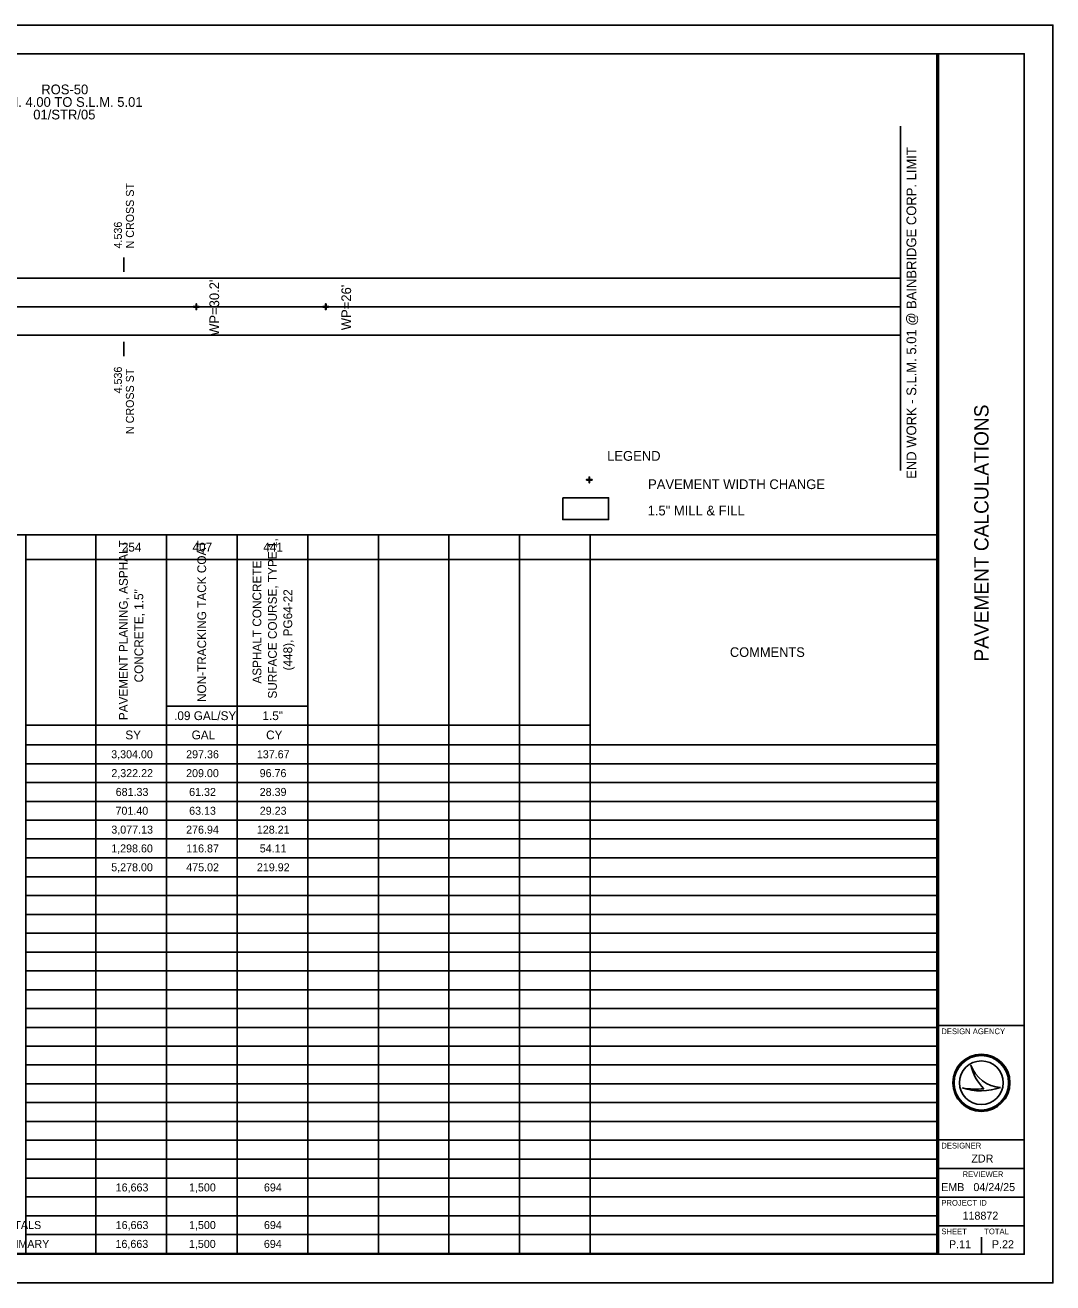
# Model space of a CAD drawing. Extents: x 0 to 34, y 0 to 42.2.
# Drawn here: x 16.03 to 34, y 0 to 22 of the extents above; entities that cross this region are included whole.
import ezdxf

# ---------------------------------------------------------------- set-up
doc = ezdxf.new("R2010")
doc.units = 0
for name, color, linetype in [('Default', 7, 'Continuous'), ('SH_Border', 7, 'Continuous'), ('SH_Cut_Line', 7, 'Continuous'), ('SH_Data', 7, 'Continuous'), ('SH_Text', 7, 'Continuous'), ('TX_P_1', 7, 'Continuous')]:
    doc.layers.add(name, color=color, linetype=linetype)

msp = doc.modelspace()

# ---------------------------------------------------------------- linework, layer by layer
at = {"layer": 'Default'}
for p, q in [((18.97, 17.079), (19.015, 17.079)), ((18.97, 17.079), (18.97, 17.069)), ((18.97, 17.069), (19.015, 17.069)), ((19.015, 17.124), (19.025, 17.124)), ((19.015, 17.079), (19.015, 17.124)), ((19.015, 17.074), (19.025, 17.074)), ((19.015, 17.024), (19.015, 17.069)), ((19.025, 17.024), (19.015, 17.024)), ((19.02, 17.069), (19.02, 17.079)), ((19.025, 17.079), (19.025, 17.124)), ((19.025, 17.079), (19.07, 17.079)), ((19.025, 17.024), (19.025, 17.069)), ((19.025, 17.069), (19.07, 17.069)), ((19.07, 17.079), (19.07, 17.069)), ((21.234, 17.079), (21.279, 17.079)), ((21.234, 17.079), (21.234, 17.069)), ((21.234, 17.069), (21.279, 17.069)), ((21.279, 17.124), (21.289, 17.124)), ((21.279, 17.079), (21.279, 17.124)), ((21.279, 17.074), (21.289, 17.074)), ((21.279, 17.024), (21.279, 17.069)), ((21.289, 17.024), (21.279, 17.024)), ((21.284, 17.069), (21.284, 17.079)), ((21.289, 17.079), (21.289, 17.124)), ((21.289, 17.079), (21.334, 17.079)), ((21.289, 17.024), (21.289, 17.069)), ((21.289, 17.069), (21.334, 17.069)), ((21.334, 17.079), (21.334, 17.069)), ((25.888, 14.096), (25.898, 14.096)), ((25.888, 14.051), (25.888, 14.096)), ((25.898, 14.051), (25.898, 14.096)), ((25.843, 14.051), (25.888, 14.051)), ((25.843, 14.051), (25.843, 14.041)), ((25.843, 14.041), (25.888, 14.041)), ((25.888, 14.046), (25.898, 14.046)), ((25.888, 13.996), (25.888, 14.041)), ((25.898, 13.996), (25.888, 13.996)), ((25.893, 14.041), (25.893, 14.051)), ((25.898, 14.051), (25.943, 14.051)), ((25.898, 13.996), (25.898, 14.041)), ((25.898, 14.041), (25.943, 14.041)), ((25.943, 14.051), (25.943, 14.041))]:
    msp.add_line(p, q, dxfattribs=at)
for points in [[(18.97, 17.069), (18.97, 17.079), (19.015, 17.079), (19.015, 17.124), (19.025, 17.124), (19.025, 17.079), (19.07, 17.079), (19.07, 17.069), (19.025, 17.069), (19.025, 17.024), (19.015, 17.024), (19.015, 17.069)], [(21.234, 17.069), (21.234, 17.079), (21.279, 17.079), (21.279, 17.124), (21.289, 17.124), (21.289, 17.079), (21.334, 17.079), (21.334, 17.069), (21.289, 17.069), (21.289, 17.024), (21.279, 17.024), (21.279, 17.069)], [(25.843, 14.041), (25.843, 14.051), (25.888, 14.051), (25.888, 14.096), (25.898, 14.096), (25.898, 14.051), (25.943, 14.051), (25.943, 14.041), (25.898, 14.041), (25.898, 13.996), (25.888, 13.996), (25.888, 14.041)]]:
    msp.add_lwpolyline(points, close=True, dxfattribs=at)
at = {"layer": 'SH_Border'}
for p, q in [((32, 0.5), (32, 21.5)), ((32, 4.5), (33.5, 4.5)), ((32, 2.5), (33.5, 2.5)), ((32, 2), (33.5, 2)), ((32, 1.5), (33.5, 1.5)), ((32, 1), (33.5, 1))]:
    msp.add_line(p, q, dxfattribs=at)
msp.add_lwpolyline([(1.5, 21.5), (33.5, 21.5), (33.5, 0.5), (1.5, 0.5)], close=True, dxfattribs=at)
at = {"layer": 'SH_Cut_Line'}
msp.add_lwpolyline([(0, 0), (34, 0), (34, 22), (0, 22)], close=True, dxfattribs=at)
at = {"layer": 'SH_Data'}
for p, q in [((32.567, 3.81), (32.567, 3.81)), ((32.417, 3.41), (32.417, 3.41)), ((32.75, 3.5), (32.75, 3.5)), ((33.087, 3.419), (33.087, 3.419)), ((32.375, 0.675), (32.375, 0.675)), ((32.75, 0.5), (32.75, 0.8))]:
    msp.add_line(p, q, dxfattribs=at)
for radius in [0.5, 0.477, 0.477, 0.382]:
    msp.add_circle((32.75, 3.5), radius, dxfattribs=at)
for centre, radius, start, end in [((33.116, 3.998), 0.58, 198.9257, 198.9319), ((33.347, 3.97), 0.796, 191.6379, 191.6421), ((33.116, 3.998), 0.58, 198.9319, 267.1657), ((33.347, 3.97), 0.796, 191.6421, 226.0947), ((32.739, 4.37), 1.013, 251.4576, 290.0832), ((32.648, 4.654), 1.266, 259.4964, 259.4995), ((32.739, 4.37), 1.013, 251.4527, 251.4576), ((32.648, 4.654), 1.266, 259.4995, 276.6672)]:
    msp.add_arc(centre, radius, start, end, dxfattribs=at)
at = {"layer": 'SH_Text'}
for p, q in [((1.5, 21.5), (31.971, 21.5)), ((31.971, 21.5), (31.971, 0.516)), ((31.335, 20.232), (31.335, 14.211)), ((17.751, 17.687), (17.751, 17.937)), ((2.18, 17.574), (31.335, 17.574)), ((2.18, 17.074), (31.335, 17.072)), ((2.18, 16.576), (31.335, 16.576)), ((17.751, 16.461), (17.751, 16.211)), ((13.891, 13.084), (16.038, 13.084)), ((16.016, 13.084), (31.971, 13.084)), ((16.038, 13.084), (16.038, 0.516)), ((17.262, 13.084), (17.262, 0.516)), ((18.498, 13.084), (18.498, 0.516)), ((19.733, 13.084), (19.733, 0.516)), ((20.968, 13.084), (20.968, 0.516)), ((22.204, 13.084), (22.204, 0.516)), ((23.439, 13.084), (23.439, 0.516)), ((24.674, 13.084), (24.674, 0.516)), ((25.909, 13.084), (25.909, 0.516)), ((16.038, 12.655), (31.971, 12.655)), ((18.498, 10.086), (20.968, 10.086)), ((16.038, 9.756), (25.909, 9.756)), ((16.038, 9.411), (31.971, 9.411)), ((16.038, 9.081), (31.971, 9.081)), ((16.038, 8.752), (31.971, 8.752)), ((16.038, 8.422), (31.971, 8.422)), ((16.038, 8.093), (31.971, 8.093)), ((16.038, 7.764), (31.971, 7.764)), ((16.038, 7.434), (31.971, 7.434)), ((16.038, 7.105), (31.971, 7.105)), ((16.038, 6.775), (31.971, 6.775)), ((16.038, 6.446), (31.971, 6.446)), ((16.038, 6.116), (31.971, 6.116)), ((16.038, 5.787), (31.971, 5.787)), ((16.038, 5.458), (31.971, 5.458)), ((16.038, 5.128), (31.971, 5.128)), ((16.038, 4.799), (31.971, 4.799)), ((16.038, 4.469), (31.971, 4.469)), ((16.038, 4.14), (31.971, 4.14)), ((16.038, 3.811), (31.971, 3.811)), ((16.038, 3.481), (31.971, 3.481)), ((16.038, 3.152), (31.971, 3.152)), ((16.038, 2.822), (31.971, 2.822)), ((16.038, 2.493), (31.971, 2.493)), ((16.038, 2.164), (31.971, 2.164)), ((16.038, 1.834), (31.971, 1.834)), ((16.038, 1.505), (31.971, 1.505)), ((16.038, 1.175), (31.971, 1.175)), ((16.038, 0.846), (31.971, 0.846)), ((1.5, 0.516), (16.038, 0.516)), ((16.016, 0.516), (31.971, 0.516))]:
    msp.add_line(p, q, dxfattribs=at)
for points in [[(2.18, 17.574), (31.335, 17.574), (31.335, 16.575), (2.18, 16.575)], [(25.43, 13.732), (26.23, 13.732), (26.23, 13.352), (25.43, 13.352)]]:
    msp.add_lwpolyline(points, close=True, dxfattribs=at)
at = {"layer": 'TX_P_1'}
msp.add_lwpolyline([(25.43, 13.732), (26.23, 13.732), (26.23, 13.352), (25.43, 13.352)], close=True, dxfattribs=at)

# ---------------------------------------------------------------- texts
at = {"layer": 'SH_Data'}
msp.add_text('PAVEMENT CALCULATIONS', height=0.25, rotation=90, dxfattribs=at).set_placement((32.875, 10.868))
for s, height, p in [('DESIGN AGENCY', 0.1, (32.05, 4.35)), ('DESIGNER', 0.1, (32.05, 2.35)), ('ZDR', 0.14, (32.575, 2.105)), ('REVIEWER', 0.1, (32.422, 1.85)), ('EMB', 0.14, (32.047, 1.605)), ('04/24/25', 0.14, (32.611, 1.605)), ('PROJECT ID', 0.1, (32.05, 1.35)), ('118872', 0.14, (32.421, 1.105)), ('SHEET', 0.1, (32.05, 0.85)), ('TOTAL', 0.1, (32.8, 0.85)), ('P.11', 0.14, (32.184, 0.605)), ('P.22', 0.14, (32.935, 0.605))]:
    msp.add_text(s, height=height, dxfattribs=at).set_placement(p)
at = {"layer": 'SH_Text'}
for s, height, p in [('ROS-50', 0.17, (16.309, 20.791)), ('S.L.M. 4.00 TO S.L.M. 5.01', 0.17, (15.313, 20.571)), ('01/STR/05', 0.17, (16.169, 20.351)), ('254', 0.154, (17.717, 12.792)), ('407', 0.154, (18.954, 12.792)), ('441', 0.154, (20.191, 12.792)), ('COMMENTS', 0.168, (28.352, 10.949)), ('.09 GAL/SY', 0.154, (18.632, 9.844)), ('1.5"', 0.154, (20.177, 9.844)), ('SY', 0.154, (17.779, 9.507)), ('GAL', 0.154, (18.938, 9.507)), ('CY', 0.154, (20.241, 9.507)), ('3,304.00', 0.14, (17.532, 9.176)), ('297.36', 0.14, (18.843, 9.176)), ('137.67', 0.14, (20.079, 9.176)), ('2,322.22', 0.14, (17.534, 8.846)), ('209.00', 0.14, (18.842, 8.846)), ('96.76', 0.14, (20.128, 8.846)), ('681.33', 0.14, (17.61, 8.517)), ('61.32', 0.14, (18.895, 8.517)), ('28.39', 0.14, (20.129, 8.517)), ('701.40', 0.14, (17.607, 8.188)), ('63.13', 0.14, (18.895, 8.188)), ('29.23', 0.14, (20.13, 8.188)), ('3,077.13', 0.14, (17.534, 7.858)), ('276.94', 0.14, (18.842, 7.858)), ('128.21', 0.14, (20.079, 7.858)), ('1,298.60', 0.14, (17.532, 7.529)), ('116.87', 0.14, (18.843, 7.529)), ('54.11', 0.14, (20.13, 7.529)), ('5,278.00', 0.14, (17.532, 7.199)), ('475.02', 0.14, (18.844, 7.199)), ('219.92', 0.14, (20.08, 7.199)), ('16,663', 0.14, (17.61, 1.599)), ('1,500', 0.14, (18.893, 1.599)), ('694', 0.14, (20.203, 1.599)), ('THIS SHEET TOTALS', 0.14, (14.424, 0.941)), ('16,663', 0.14, (17.61, 0.941)), ('1,500', 0.14, (18.893, 0.941)), ('694', 0.14, (20.203, 0.941)), ('TOTALS CARRIED TO GENERAL SUMMARY', 0.14, (12.559, 0.611)), ('16,663', 0.14, (17.607, 0.611)), ('1,500', 0.14, (18.891, 0.611)), ('694', 0.14, (20.202, 0.611))]:
    msp.add_text(s, height=height, dxfattribs=at).set_placement(p)
for s, height, p in [('END WORK - S.L.M. 5.01 @ BAINBRIDGE CORP. LIMIT', 0.17, (31.611, 14.064)), ('N CROSS ST', 0.14, (17.929, 18.094)), ('4.536', 0.14, (17.719, 18.094)), ("WP=30.2'", 0.17, (19.42, 16.565)), ("WP=26'", 0.17, (21.728, 16.664)), ('4.536', 0.14, (17.719, 15.558)), ('N CROSS ST', 0.14, (17.929, 14.847)), ('PAVEMENT PLANING, ASPHALT ', 0.154, (17.822, 9.843)), ('NON-TRACKING TACK COAT', 0.154, (19.192, 10.16)), ('SURFACE COURSE, TYPE 1, ', 0.154, (20.428, 10.22)), ('ASPHALT CONCRETE ', 0.154, (20.158, 10.482)), ('CONCRETE, 1.5"', 0.154, (18.092, 10.503)), ('(448), PG64-22', 0.154, (20.697, 10.713))]:
    msp.add_text(s, height=height, rotation=90, dxfattribs=at).set_placement(p)
at = {"layer": 'TX_P_1'}
for s, p in [('LEGEND', (26.205, 14.38)), ('PAVEMENT WIDTH CHANGE', (26.921, 13.885)), ('1.5" MILL & FILL', (26.913, 13.424))]:
    msp.add_text(s, height=0.17, dxfattribs=at).set_placement(p)

doc.saveas('drawing.dxf')
